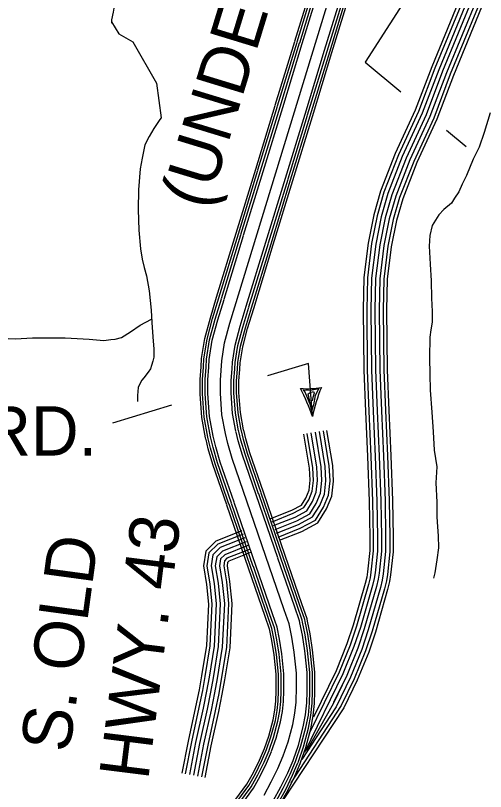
# Model space of a CAD drawing. Extents: x 1551132 to 1791609, y 378168 to 563823.
# Drawn here: x 1589174 to 1592691, y 408950 to 414761 of the extents above; entities that cross this region are included whole.
import ezdxf

# ---------------------------------------------------------------- set-up
doc = ezdxf.new("R2010")
doc.units = 0
for name, color, linetype in [('DESIGN - ROW - Right-of-Way and Easement Labels', 7, 'Continuous'), ('DESIGN - TRANSPORTATION - Text', 7, 'Continuous'), ('SURVEY - CENTERLINE - Preliminary Text', 7, 'Continuous'), ('SURVEY - TRANSPORTATION - Roads', 7, 'Continuous')]:
    doc.layers.add(name, color=color, linetype=linetype)

msp = doc.modelspace()

# ---------------------------------------------------------------- linework, layer by layer
at = {"layer": 'DESIGN - ROW - Right-of-Way and Easement Labels'}
for p, q in [((1591381.907, 411955.15), (1591443.789, 411967.775)), ((1591443.789, 411967.775), (1591415.723, 411914.448)), ((1591341.316, 411939.399), (1591329.833, 411956.85)), ((1591329.833, 411956.85), (1591381.907, 411955.15)), ((1591360.274, 411899.015), (1591341.316, 411939.399)), ((1591365.141, 411928.949), (1591379.49, 411938.116)), ((1591392.448, 411806.196), (1591365.141, 411928.949)), ((1591379.49, 411938.116), (1591405.623, 411946.808)), ((1591408.465, 411932.107), (1591400.498, 411899.898)), ((1591415.723, 411914.448), (1591404.323, 411844.93)), ((1591405.623, 411946.808), (1591408.465, 411932.107)), ((1591378.649, 411850.055), (1591360.274, 411899.015)), ((1591394.131, 411793.587), (1591378.649, 411850.055)), ((1591400.498, 411899.898), (1591395.415, 411875.247)), ((1591404.323, 411844.93), (1591392.448, 411806.196))]:
    msp.add_line(p, q, dxfattribs=at)
for points in [[(1592160.707, 414987.421), (1591790.982, 414411.606), (1592057.434, 414188.734)], [(1592400.018, 413902.185), (1592545.864, 413780.198)], [(1591395.781, 411758.428), (1591367.241, 412155.68), (1591060.348, 412062.16)], [(1590341.398, 411843.071), (1589899.483, 411708.4)]]:
    msp.add_lwpolyline(points, dxfattribs=at)
for centre, radius, start, end in [((1591359.166, 412498.443), 532.284, 264.4048833, 281.2632806), ((1589924.751, 411262.8), 1552.303, 18.6204333, 27.0482111), ((1592749.602, 411459.616), 1386.393, 158.1139472, 167.5524861)]:
    msp.add_arc(centre, radius, start, end, dxfattribs=at)
at = {"layer": 'DESIGN - TRANSPORTATION - Text'}
for points in [[(1590014.583, 415615.545), (1589965.092, 415556.827), (1589952.934, 415542.951), (1589938.776, 415529.101), (1589922.26, 415483.233), (1589899.477, 415413.406), (1589882.836, 415355.521), (1589884.452, 415321.454), (1589903.935, 415275.169), (1589931.193, 415208.759), (1589936.859, 415178.65), (1589923.801, 415084.673), (1589916.71, 414986.628), (1589920.035, 414926.51), (1589917.293, 414860.45), (1589904.468, 414786.498), (1589893.818, 414728.547), (1589893.552, 414704.896)], [(1589893.635, 414712.529), (1589948.05, 414624.252), (1590051.84, 414564.909), (1590229.752, 414253.401), (1590263.634, 413993.711), (1590253.493, 413983.335), (1590208.736, 413915.767), (1590174.045, 413854.09), (1590143.354, 413792.364), (1590122.229, 413692.478), (1590107.338, 413612.542), (1590095.563, 413454.471), (1590091.93, 413308.318), (1590098.204, 413154.039), (1590108.637, 413013.727), (1590121.762, 412935.466), (1590137.062, 412873.206), (1590154.386, 412812.921), (1590175.136, 412700.527), (1590189.493, 412554.156), (1590194.46, 412461.979), (1590203.251, 412353.726), (1590210.218, 412261.524), (1590209.568, 412203.455), (1590201.21, 412171.504), (1590190.852, 412139.587), (1590184.585, 412115.628), (1590166.294, 412089.802), (1590133.828, 412048.126), (1590119.628, 412030.267), (1590107.387, 412008.383), (1590091.029, 411976.533), (1590086.354, 411916.506), (1590086.395, 411871.296)], [(1592725.827, 414031.58), (1592682.178, 413883.893), (1592642.97, 413776.207), (1592599.938, 413684.587), (1592550.581, 413563.001), (1592515.84, 413497.316), (1592491.215, 413441.531), (1592460.683, 413393.821), (1592436.258, 413356.062), (1592379.726, 413308.661), (1592343.285, 413269.035), (1592316.836, 413229.284), (1592292.37, 413187.516), (1592275.537, 413113.614), (1592270.645, 413033.562), (1592277.145, 412899.308), (1592283.753, 412775.063), (1592286.294, 412644.86), (1592293.169, 412544.641), (1592292.278, 412464.547), (1592281.628, 412406.587), (1592275.02, 412352.594), (1592273.294, 412198.407), (1592273.928, 412076.237), (1592276.586, 411956.042), (1592290.744, 411791.654), (1592299.085, 411643.359), (1592307.56, 411507.072), (1592328.151, 411380.668), (1592320.801, 411260.59), (1592327.193, 411116.32), (1592327.976, 411008.167), (1592331.126, 410932.023), (1592336.367, 410863.871), (1592339.375, 410775.719), (1592328.367, 410685.725), (1592311.276, 410587.797), (1592301.376, 410546.571)], [(1588683.887, 412082.826), (1588698.386, 412103.002), (1588785.609, 412212.13), (1588809.992, 412245.889), (1588834.325, 412275.64), (1588854.458, 412287.423), (1588912.74, 412312.774), (1588988.888, 412325.899), (1589065.111, 412345.033), (1589175.05, 412339.742), (1589301.131, 412346.275), (1589405.145, 412347.059), (1589545.158, 412347.417), (1589725.046, 412337.3), (1589834.952, 412328), (1589887.034, 412335.4), (1589921.05, 412337.009), (1589967.207, 412350.484), (1590033.672, 412391.76), (1590108.245, 412442.962), (1590193.16, 412486.054)]]:
    msp.add_lwpolyline(points, dxfattribs=at)
at = {"layer": 'SURVEY - CENTERLINE - Preliminary Text'}
for points in [[(1591034.313, 408923.711), (1591088.77, 409021.747), (1591137.769, 409122.508), (1591178.61, 409217.819), (1591214.001, 409321.305), (1591249.392, 409452.017), (1591265.725, 409536.436), (1591274.383, 409618.221), (1591276.616, 409735.233), (1591276.616, 409835.994), (1591260.092, 409992.539), (1591242.234, 410106.909), (1591222.168, 410206.353), (1591185.877, 410311.364), (1590795.62, 411444.786), (1590763.063, 411556.139), (1590745.197, 411630.866), (1590719.214, 411770.586), (1590707.848, 411933.049), (1590707.848, 412030.518), (1590717.589, 412175.113), (1590738.705, 412309.95), (1590777.955, 412456.346), (1592043.086, 416594.797)], [(1591265.161, 414568.185), (1591411.341, 415046.348)], [(1591281.894, 414563.068), (1591428.074, 415041.231)], [(1591301.027, 414557.218), (1591447.207, 415035.381)], [(1591320.685, 414552.159), (1591466.857, 415030.322)], [(1592548.531, 414940.262), (1592313.02, 414366.264), (1592189.939, 414041.363), (1592040.451, 413717.58), (1591931.403, 413437.031), (1591881.138, 413261.718), (1591839.289, 413052.712), (1591807.547, 412796.855), (1591802.489, 412556.224), (1591806.697, 412105.262), (1591819.53, 411797.462), (1591834.179, 411458.762), (1591846.812, 411124.753), (1591851.453, 410855.938), (1591851.453, 410752.393), (1591833.97, 410592.006), (1591827.812, 410551.338), (1591815.287, 410501.203), (1591725.481, 410187.353), (1591677.832, 410046.324), (1591596.317, 409843.911), (1591373.105, 409385.382)], [(1592524.915, 414950.454), (1592289.096, 414375.697), (1592166.215, 414051.322), (1592016.768, 413727.638), (1591907.004, 413445.247), (1591856.13, 413267.793), (1591813.881, 413056.829), (1591781.865, 412798.705), (1591776.773, 412556.374), (1591780.989, 412104.612), (1591793.83, 411796.371), (1591808.488, 411457.72), (1591821.104, 411124.045), (1591825.737, 410855.713), (1591825.737, 410753.793), (1591808.463, 410595.322), (1591802.571, 410556.388), (1591790.446, 410507.853), (1591700.923, 410195.012), (1591653.708, 410055.25), (1591572.801, 409854.353), (1591403.855, 409507.268)], [(1591487.498, 414501.158), (1591633.67, 414979.321)], [(1591506.889, 414495.233), (1591653.061, 414973.396)], [(1591526.013, 414489.383), (1591672.185, 414967.546)], [(1591542.755, 414484.266), (1591688.927, 414962.429)], [(1592685.095, 414881.327), (1592451.375, 414311.679), (1592327.153, 413983.779), (1592177.389, 413659.412), (1592072.483, 413389.496), (1592025.768, 413226.558), (1591986.185, 413028.92), (1591956.069, 412786.105), (1591951.219, 412555.357), (1591955.385, 412109.054), (1591968.11, 411803.779), (1591982.767, 411464.787), (1591995.484, 411128.845), (1592000.167, 410857.221), (1592000.167, 410744.31), (1591981.467, 410572.814), (1591973.8, 410522.129), (1591958.959, 410462.711), (1591867.494, 410143.069), (1591817.362, 409994.698), (1591732.314, 409783.509), (1591631.924, 409577.279), (1591104.52, 408778.866)], [(1592662.395, 414891.128), (1592428.384, 414320.746), (1592304.353, 413993.345), (1592154.632, 413669.078), (1592049.034, 413397.396), (1592001.735, 413232.4), (1591961.769, 413032.878), (1591931.378, 412787.888), (1591926.503, 412555.507), (1591930.677, 412108.429), (1591943.41, 411802.729), (1591958.076, 411463.779), (1591970.776, 411128.17), (1591975.451, 410857.004), (1591975.451, 410745.66), (1591956.951, 410576.005), (1591949.543, 410526.987), (1591935.085, 410469.102), (1591843.895, 410150.436), (1591794.179, 410003.273), (1591709.714, 409793.543), (1591611.425, 409595.088), (1591235.442, 409014.389)], [(1592633.929, 414903.411), (1592399.543, 414332.129), (1592275.746, 414005.354), (1592126.091, 413681.204), (1592019.626, 413407.305), (1591971.586, 413239.734), (1591931.153, 413037.837), (1591900.42, 412790.13), (1591895.495, 412555.682), (1591899.678, 412107.637), (1591912.444, 411801.412), (1591927.102, 411462.529), (1591939.785, 411127.311), (1591944.451, 410856.738), (1591944.451, 410747.343), (1591926.21, 410580.005), (1591919.11, 410533.071), (1591905.135, 410477.128), (1591814.287, 410159.661), (1591765.088, 410014.04), (1591681.365, 409806.135), (1591573.426, 409584.412), (1591569.009, 409576.462), (1591316.907, 409190.727)], [(1592576.997, 414927.978), (1592341.861, 414354.88), (1592218.547, 414029.355), (1592068.992, 413705.454), (1591960.811, 413427.122), (1591911.287, 413254.384), (1591869.904, 413047.754), (1591838.505, 412794.614), (1591833.497, 412556.049), (1591837.696, 412106.054), (1591850.496, 411798.779), (1591865.154, 411460.012), (1591877.803, 411125.611), (1591882.453, 410856.204), (1591882.453, 410750.71), (1591864.711, 410588.006), (1591858.245, 410545.254), (1591845.237, 410493.178), (1591755.089, 410178.128), (1591706.923, 410035.558), (1591624.666, 409831.319), (1591337.523, 409241.453)], [(1592605.463, 414915.695), (1592370.702, 414343.505), (1592247.146, 414017.354), (1592097.541, 413693.329), (1591990.219, 413417.213), (1591941.436, 413247.059), (1591900.529, 413042.795), (1591869.463, 412792.372), (1591864.496, 412555.866), (1591868.687, 412106.846), (1591881.47, 411800.096), (1591896.128, 411461.27), (1591908.794, 411126.461), (1591913.452, 410856.471), (1591913.452, 410749.026), (1591895.461, 410584.005), (1591888.677, 410539.163), (1591875.186, 410485.153), (1591784.688, 410168.894), (1591736.006, 410024.799), (1591653.016, 409818.727), (1591550.368, 409607.863), (1591351.372, 409254.578)], [(1592605.463, 414915.695), (1592370.702, 414343.505), (1592247.146, 414017.354), (1592097.541, 413693.329), (1591990.219, 413417.213), (1591941.436, 413247.059), (1591900.529, 413042.795), (1591869.463, 412792.372), (1591864.496, 412555.866), (1591868.687, 412106.846), (1591881.47, 411800.096), (1591896.128, 411461.27), (1591908.794, 411126.461), (1591913.452, 410856.471), (1591913.452, 410749.026), (1591895.461, 410584.005), (1591888.677, 410539.163), (1591875.186, 410485.153), (1591784.688, 410168.894), (1591736.006, 410024.799), (1591653.016, 409818.727), (1591554.668, 409616.696)], [(1591118.723, 414089.147), (1591264.895, 414567.31)], [(1591135.456, 414084.03), (1591281.628, 414562.193)], [(1591154.58, 414078.18), (1591300.752, 414556.343)], [(1591174.246, 414073.122), (1591320.418, 414551.293)], [(1591341.059, 414022.121), (1591487.231, 414500.292)], [(1591360.45, 414016.195), (1591506.622, 414494.366)], [(1591379.575, 414010.345), (1591525.747, 414488.516)], [(1591396.316, 414005.228), (1591542.488, 414483.399)], [(1590972.276, 413610.109), (1591118.456, 414088.28)], [(1590989.009, 413604.993), (1591135.189, 414083.164)], [(1591008.142, 413599.143), (1591154.322, 414077.314)], [(1591027.8, 413594.084), (1591173.98, 414072.255)], [(1591194.612, 413543.083), (1591340.792, 414021.254)], [(1591214.003, 413537.149), (1591360.184, 414015.32)], [(1591233.128, 413531.308), (1591379.308, 414009.479)], [(1591249.869, 413526.191), (1591396.05, 414004.362)], [(1590825.837, 413131.072), (1590972.009, 413609.243)], [(1590842.57, 413125.955), (1590988.742, 413604.126)], [(1590861.695, 413120.105), (1591007.867, 413598.276)], [(1590881.361, 413115.055), (1591027.533, 413593.217)], [(1591048.174, 413064.053), (1591194.346, 413542.216)], [(1591067.565, 413058.128), (1591213.737, 413536.291)], [(1591086.689, 413052.278), (1591232.861, 413530.441)], [(1591103.431, 413047.161), (1591249.603, 413525.324)], [(1590679.39, 412652.042), (1590825.571, 413130.205)], [(1590696.123, 412646.926), (1590842.304, 413125.088)], [(1590715.256, 412641.075), (1590861.436, 413119.238)], [(1590734.914, 412636.017), (1590881.094, 413114.18)], [(1590901.727, 412585.016), (1591047.907, 413063.178)], [(1590921.118, 412579.082), (1591067.298, 413057.245)], [(1590940.243, 412573.241), (1591086.423, 413051.403)], [(1590956.984, 412568.124), (1591103.164, 413046.286)], [(1590562.801, 412130.87), (1590566.918, 412191.955), (1590590.317, 412341.368), (1590632.341, 412498.113), (1590679.132, 412651.167)], [(1590580.259, 412129.695), (1590584.326, 412190.005), (1590607.459, 412337.742), (1590649.166, 412493.288), (1590695.873, 412646.051)], [(1590600.217, 412128.345), (1590604.217, 412187.788), (1590627.058, 412333.592), (1590668.391, 412487.771), (1590714.998, 412640.209)], [(1590620.508, 412127.895), (1590624.4, 412185.53), (1590646.924, 412329.384), (1590687.89, 412482.18), (1590734.647, 412635.142)], [(1590794.546, 412116.162), (1590797.912, 412166.13), (1590817.812, 412293.2), (1590855.586, 412434.078), (1590901.46, 412584.149)], [(1590814.787, 412114.795), (1590818.095, 412163.88), (1590837.686, 412288.991), (1590875.086, 412428.487), (1590920.851, 412578.224)], [(1590834.736, 412113.453), (1590837.986, 412161.655), (1590857.278, 412284.841), (1590894.31, 412422.97), (1590939.984, 412572.374)], [(1590852.194, 412112.278), (1590855.394, 412159.705), (1590874.427, 412281.216), (1590911.135, 412418.145), (1590956.717, 412567.257)], [(1590599.758, 411587.789), (1590596.992, 411599.398), (1590568.726, 411751.394), (1590556.384, 411927.757), (1590556.385, 412035.618), (1590562.743, 412129.962)], [(1590616.783, 411591.856), (1590614.108, 411603.031), (1590586.109, 411753.61), (1590573.884, 411928.365), (1590573.884, 412035.026), (1590580.201, 412128.787)], [(1590636.232, 411596.498), (1590633.682, 411607.19), (1590605.983, 411756.144), (1590593.884, 411929.065), (1590593.884, 412034.351), (1590600.159, 412127.445)], [(1590655.765, 411602.065), (1590653.532, 411611.39), (1590626.133, 411758.711), (1590614.166, 411929.773), (1590614.167, 412033.668), (1590620.45, 412126.987)], [(1590825.403, 411642.658), (1590824.203, 411647.658), (1590799.445, 411780.82), (1590788.596, 411935.874), (1590788.596, 412027.801), (1590794.487, 412115.262)], [(1590845.128, 411647.374), (1590844.053, 411651.875), (1590819.595, 411783.386), (1590808.879, 411936.582), (1590808.879, 412027.118), (1590814.729, 412113.895)], [(1590864.577, 411652.033), (1590863.619, 411656.033), (1590839.469, 411785.928), (1590828.878, 411937.274), (1590828.878, 412026.443), (1590834.678, 412112.553)], [(1590881.602, 411656.108), (1590880.743, 411659.666), (1590856.852, 411788.145), (1590846.378, 411937.89), (1590846.378, 412025.859), (1590852.136, 412111.37)], [(1590974.608, 411172.987), (1590872.585, 411469.278), (1590841.128, 411576.873), (1590825.611, 411641.766)], [(1590993.782, 411179.587), (1590891.926, 411475.428), (1590860.735, 411582.081), (1590845.344, 411646.483)], [(1591012.698, 411186.104), (1590910.984, 411481.495), (1590880.077, 411587.215), (1590864.794, 411651.133)], [(1591029.24, 411191.796), (1590927.667, 411486.804), (1590896.993, 411591.706), (1590881.81, 411655.2)], [(1590755.338, 411096.527), (1590651.249, 411398.851), (1590616.633, 411517.246), (1590599.983, 411586.864)], [(1590771.887, 411102.218), (1590667.923, 411404.16), (1590633.549, 411521.738), (1590617, 411590.939)], [(1590790.795, 411108.735), (1590686.989, 411410.218), (1590652.882, 411526.871), (1590636.449, 411595.59)], [(1590809.686, 411116.194), (1590706.322, 411416.377), (1590672.49, 411532.08), (1590655.965, 411601.19)], [(1591137.687, 410699.358), (1590974.899, 411172.129)], [(1591156.861, 410705.958), (1590994.074, 411178.729)], [(1591175.778, 410712.475), (1591012.99, 411185.246)], [(1591192.319, 410718.167), (1591029.531, 411190.938)], [(1590918.417, 410622.889), (1590755.638, 411095.66)], [(1590934.966, 410628.589), (1590772.187, 411101.36)], [(1590953.874, 410635.106), (1590791.095, 411107.877)], [(1590972.766, 410642.565), (1590809.978, 411115.335)], [(1591302.758, 410215.245), (1591300.241, 410227.646), (1591262.209, 410337.699), (1591137.978, 410698.5)], [(1591322.632, 410219.262), (1591319.857, 410232.996), (1591281.383, 410344.315), (1591157.153, 410705.1)], [(1591342.24, 410223.229), (1591339.198, 410238.263), (1591300.291, 410350.832), (1591176.069, 410711.617)], [(1591359.39, 410226.704), (1591356.115, 410242.879), (1591316.832, 410356.541), (1591192.61, 410717.309)], [(1591112.07, 410175.803), (1591111.962, 410176.344), (1591078.146, 410274.197), (1590954.174, 410634.248)], [(1591131.787, 410180.644), (1591131.587, 410181.653), (1591097.321, 410280.814), (1590973.057, 410641.706)], [(1591075.696, 410166.461), (1591042.697, 410261.971), (1590918.717, 410622.031)], [(1591092.621, 410171.077), (1591059.238, 410267.672), (1590935.266, 410627.731)], [(1591414.496, 409699.782), (1591415.146, 409733.916), (1591415.146, 409843.286), (1591397.497, 410010.507), (1591378.631, 410131.31), (1591359.573, 410225.746)], [(1591124.536, 409704.398), (1591125.153, 409736.674), (1591125.153, 409828.018), (1591109.862, 409972.889), (1591093.104, 410080.233), (1591075.496, 410167.486)], [(1591142.036, 409704.065), (1591142.653, 409736.508), (1591142.653, 409828.943), (1591127.22, 409975.164), (1591110.329, 410083.317), (1591092.654, 410170.944)], [(1591162.027, 409703.682), (1591162.652, 409736.316), (1591162.652, 409829.993), (1591147.053, 409977.756), (1591130.02, 410086.834), (1591112.254, 410174.903)], [(1591182.327, 409704.207), (1591182.935, 409736.124), (1591182.935, 409831.06), (1591167.169, 409980.389), (1591149.994, 410090.409), (1591131.953, 410179.803)], [(1591356.723, 409700.882), (1591357.364, 409734.466), (1591357.364, 409840.244), (1591340.182, 410003.015), (1591321.74, 410121.135), (1591302.941, 410214.312)], [(1591377.006, 409700.499), (1591377.647, 409734.274), (1591377.647, 409841.311), (1591360.298, 410005.648), (1591341.707, 410124.701), (1591322.815, 410218.32)], [(1591396.997, 409700.115), (1591397.647, 409734.083), (1591397.647, 409842.361), (1591380.139, 410008.24), (1591361.406, 410128.226), (1591342.423, 410222.279)], [(1591037.147, 409272.254), (1591069.088, 409365.656), (1591101.745, 409486.243), (1591115.787, 409558.836), (1591123.07, 409627.663), (1591124.52, 409703.507)], [(1591053.496, 409265.962), (1591085.837, 409360.531), (1591118.803, 409482.293), (1591133.111, 409556.253), (1591140.553, 409626.571), (1591142.019, 409703.173)], [(1591072.062, 409258.52), (1591072.171, 409258.778), (1591104.97, 409354.673), (1591138.294, 409477.768), (1591152.911, 409553.295), (1591160.536, 409625.321), (1591162.011, 409702.79)], [(1591091.054, 409251.337), (1591091.112, 409251.478), (1591124.37, 409348.739), (1591158.069, 409473.184), (1591172.985, 409550.294), (1591180.793, 409624.055), (1591182.31, 409703.307)], [(1591251.383, 409182.626), (1591254.025, 409188.81), (1591291.257, 409297.663), (1591328.106, 409433.766), (1591345.656, 409524.494), (1591355.048, 409613.188), (1591356.706, 409699.974)], [(1591270.024, 409174.635), (1591272.974, 409181.518), (1591310.657, 409291.721), (1591347.881, 409429.183), (1591365.739, 409521.494), (1591375.314, 409611.93), (1591376.989, 409699.582)], [(1591288.407, 409166.759), (1591291.649, 409174.335), (1591329.798, 409285.871), (1591367.372, 409424.666), (1591385.539, 409518.535), (1591395.288, 409610.68), (1591396.98, 409699.207)], [(1591304.49, 409159.859), (1591307.998, 409168.043), (1591346.539, 409280.746), (1591384.438, 409420.716), (1591402.863, 409515.944), (1591412.771, 409609.588), (1591414.48, 409698.865)], [(1590810.443, 408876.243), (1590824.376, 408893.527), (1590906.533, 409005.588), (1590954.365, 409091.699), (1590999.972, 409185.501), (1591037.222, 409272.42)], [(1590824.068, 408865.26), (1590838.251, 408882.86), (1590921.299, 408996.13), (1590969.89, 409083.615), (1591015.897, 409178.218), (1591053.313, 409265.529)], [(1590839.634, 408852.701), (1590854.109, 408870.66), (1590938.165, 408985.321), (1590987.639, 409074.382), (1591034.088, 409169.901), (1591071.696, 409257.653)], [(1590856, 408840.692), (1590870.2, 408858.301), (1590955.282, 408974.354), (1591005.639, 409065.015), (1591052.546, 409161.467), (1591090.695, 409250.503)], [(1590991.781, 408731.189), (1591008.497, 408751.923), (1591102.436, 408880.06), (1591160.427, 408984.455), (1591211.226, 409088.924), (1591251.025, 409181.793)], [(1591007.572, 408718.456), (1591024.58, 408739.556), (1591119.544, 408869.093), (1591178.426, 408975.088), (1591229.684, 409080.49), (1591269.666, 409173.81)], [(1591023.138, 408705.905), (1591040.438, 408727.356), (1591136.419, 408858.285), (1591196.168, 408965.854), (1591247.875, 409072.174), (1591288.049, 409165.926)], [(1591036.763, 408694.922), (1591054.312, 408716.681), (1591151.185, 408848.826), (1591211.701, 408957.771), (1591263.799, 409064.898), (1591304.132, 409159.034)]]:
    msp.add_lwpolyline(points, dxfattribs=at)
at = {"layer": 'SURVEY - TRANSPORTATION - Roads'}
for points in [[(1591084.922, 410993.816), (1591243.018, 411056.309), (1591314.158, 411094.66), (1591346.274, 411146.603), (1591370.99, 411206.563), (1591379.465, 411280.623), (1591374.757, 411372.151), (1591332.849, 411626.274)], [(1591094.005, 410970.832), (1591253.459, 411033.867), (1591331.699, 411076.043), (1591368.357, 411135.32), (1591395.148, 411200.33), (1591404.256, 411279.848), (1591399.364, 411374.809), (1591357.232, 411630.291)], [(1591105.404, 410942.006), (1591266.559, 411005.708), (1591353.707, 411052.692), (1591396.048, 411121.161), (1591425.455, 411192.504), (1591435.347, 411278.873), (1591430.239, 411378.134), (1591387.823, 411635.341)], [(1591116.796, 410913.172), (1591279.659, 410977.549), (1591375.715, 411029.333), (1591423.747, 411107.011), (1591455.763, 411184.688), (1591466.438, 411277.898), (1591461.105, 411381.468), (1591418.406, 411640.383)], [(1591116.796, 410913.172), (1591279.659, 410977.549), (1591375.715, 411029.333), (1591423.747, 411107.011), (1591455.763, 411184.688), (1591466.438, 411277.898), (1591461.105, 411381.468), (1591418.406, 411640.383)], [(1591128.187, 410884.338), (1591292.758, 410949.39), (1591397.723, 411005.975), (1591451.446, 411092.86), (1591486.071, 411176.871), (1591497.529, 411276.923), (1591491.971, 411384.801), (1591448.988, 411645.425)], [(1591139.587, 410855.512), (1591305.858, 410921.231), (1591419.73, 410982.624), (1591479.137, 411078.702), (1591516.378, 411169.046), (1591528.62, 411275.948), (1591522.845, 411388.126), (1591479.579, 411650.475)], [(1591149.037, 410831.595), (1591316.724, 410897.88), (1591437.98, 410963.248), (1591502.112, 411066.96), (1591541.519, 411162.562), (1591554.411, 411275.148), (1591548.453, 411390.893), (1591504.954, 411654.658)], [(1590869.185, 410901.955), (1590674.189, 410824.878), (1590597.966, 410750.901), (1590580.491, 410640.706), (1590603.716, 410499.886), (1590618.765, 410353.849), (1590603.332, 410044.274), (1590566.866, 409816.818), (1590547.917, 409711.723), (1590522.15, 409584.953), (1590466.018, 409327.83), (1590419.694, 409088.098)], [(1590878.635, 410878.038), (1590688.414, 410802.844), (1590622.024, 410738.409), (1590606.541, 410640.789), (1590629.215, 410503.294), (1590644.548, 410354.532), (1590628.94, 410041.582), (1590592.216, 409812.501), (1590573.174, 409706.882), (1590547.317, 409579.645), (1590491.209, 409322.646), (1590444.944, 409083.223)], [(1590890.034, 410849.212), (1590705.564, 410776.293), (1590651.023, 410723.35), (1590637.948, 410640.881), (1590659.956, 410507.411), (1590675.622, 410355.349), (1590659.823, 410038.349), (1590622.782, 409807.301), (1590603.615, 409701.048), (1590577.649, 409573.253), (1590521.575, 409316.405), (1590475.385, 409077.34)], [(1590901.426, 410820.378), (1590722.713, 410749.734), (1590680.022, 410708.3), (1590669.348, 410640.981), (1590690.697, 410511.528), (1590706.705, 410356.174), (1590690.697, 410035.115), (1590653.339, 409802.092), (1590634.065, 409695.206), (1590607.982, 409566.861), (1590551.941, 409310.154), (1590505.817, 409071.456)], [(1590901.426, 410820.378), (1590722.713, 410749.734), (1590680.022, 410708.3), (1590669.348, 410640.981), (1590690.697, 410511.528), (1590706.705, 410356.174), (1590690.697, 410035.115), (1590653.339, 409802.092), (1590634.065, 409695.206), (1590607.982, 409566.861), (1590551.941, 409310.154), (1590505.817, 409071.456)], [(1590912.817, 410791.544), (1590739.863, 410723.175), (1590709.022, 410693.249), (1590700.747, 410641.081), (1590721.438, 410515.645), (1590737.788, 410356.999), (1590721.571, 410031.882), (1590683.897, 409796.884), (1590664.514, 409689.364), (1590638.314, 409560.469), (1590582.307, 409303.904), (1590536.25, 409065.573)], [(1590924.217, 410762.718), (1590757.012, 410696.624), (1590738.021, 410678.191), (1590732.155, 410641.173), (1590752.179, 410519.761), (1590768.862, 410357.815), (1590752.454, 410028.648), (1590714.463, 409791.684), (1590694.955, 409683.531), (1590668.647, 409554.078), (1590612.673, 409297.662), (1590566.691, 409059.689)], [(1590933.3, 410739.734), (1590770.687, 410675.449), (1590761.146, 410666.19), (1590757.187, 410641.256), (1590776.687, 410523.036), (1590793.645, 410358.474), (1590777.07, 410026.065), (1590738.829, 409787.534), (1590719.229, 409678.873), (1590692.838, 409548.977), (1590636.881, 409292.679), (1590590.957, 409055.006)]]:
    msp.add_lwpolyline(points, dxfattribs=at)

# ---------------------------------------------------------------- texts
at = {"layer": 'DESIGN - ROW - Right-of-Way and Easement Labels'}
for s, height, rotation, p in [('(UNDER ', 370.0083, 73.0015222, (1590612.017, 413297.859)), ('JACKSON RD.', 369.99134, 0.0000361, (1586458.138, 411465.633)), ('HWY. 43', 370.0095, 82.9155139, (1590166.917, 409029.855)), ('S. OLD', 370.0095, 82.2679389, (1589577.714, 409234.435))]:
    msp.add_text(s, height=height, rotation=rotation, dxfattribs=at).set_placement(p)

doc.saveas('drawing.dxf')
